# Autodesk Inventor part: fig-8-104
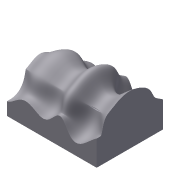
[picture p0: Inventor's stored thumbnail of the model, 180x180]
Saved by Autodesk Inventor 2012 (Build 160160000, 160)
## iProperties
Shininess: 64.0
Length Units: 11269
Angle Units: 11279
Time Units: 11290
Mass Units: 11283
Length Display Precision: 3
Angle Display Precision: 2
Compacted: True
Part Number: fig-8-104
Document SubType Name: Modeling
Created: 2002-12
Designer: deepak
Density: 1 g/cm^3
Material: Default
Density: 0.0
Volumn: 0.0
Area: 0.0
PropertySet Name: Model Information
Control State: 0
Master: False
Checked Out: False
Author: deepak
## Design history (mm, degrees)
sketch "Sketch1"
  geometry: L1 (-34.987, 25.636)-(31.934, 25.636); L2 (31.934, 25.636)-(31.934, -23.728); L3 (31.934, -23.728)-(-34.987, -23.728); L4 (-34.987, -23.728)-(-34.987, 25.636)
  constraints: 8 end point, 2 parallel, 1 horizontal, 1 perpendicular
extrude "Extrusion1" new body sketch "Sketch1" distance "d0" = 25; taper "d1" = 0 deg
sketch "Sketch2"
  geometry: 14 further points
  constraints: 14 other
workplane "Work Plane1"
sketch "Sketch3"
  geometry: 8 further points
  constraints: 8 other
feature "SweepSrf1" sketch "Sketch3" dims "d2" = 0
feature "Replace Face3"
body "Solid1"
body "Srf1"
